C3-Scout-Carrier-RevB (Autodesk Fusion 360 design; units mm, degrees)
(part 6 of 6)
sketch "Antenna clearance cutout outline" plane through (0, 0, 0) normal (0, 0, 1) x axis (1, 0, 0)
  line L1 (23, 56) -> (11, 56)
  line L2 (23, 63) -> (23, 56)
  line L3 (11, 63) -> (23, 63)
  line L4 (11, 56) -> (11, 63)
extrude "Extrude2" cut sketch "Antenna clearance cutout outline" along normal blind 1.6
sketch "M3 NPTH clearance mounting holes profile" plane through (0, 0, 0) normal (0, 0, 1) x axis (1, 0, 0)
  circle C1 centre (3, 3) radius 1.7
  circle C2 centre (29, 3) radius 1.7
  circle C3 centre (3, 79) radius 1.7
  circle C4 centre (29, 79) radius 1.7
extrude "Extrude3" cut sketch "M3 NPTH clearance mounting holes profile" along normal blind 1.6
sketch "Plated holes 0.8 profile" plane through (0, 0, 0) normal (0, 0, 1) x axis (1, 0, 0)
  circle C1 centre (25.75, 16) radius 0.4
  circle C2 centre (28.25, 16) radius 0.4
extrude "Extrude4" cut sketch "Plated holes 0.8 profile" along normal blind 1.6
sketch "Plated holes 1.05 profile" plane through (0, 0, 0) normal (0, 0, 1) x axis (1, 0, 0)
  circle C1 centre (9.38, 77.14) radius 0.525
  circle C2 centre (9.38, 74.6) radius 0.525
  circle C3 centre (9.38, 72.06) radius 0.525
  circle C4 centre (9.38, 69.52) radius 0.525
  circle C5 centre (9.38, 66.98) radius 0.525
  circle C6 centre (9.38, 64.44) radius 0.525
  circle C7 centre (9.38, 61.9) radius 0.525
  circle C8 centre (9.38, 59.36) radius 0.525
  circle C9 centre (24.62, 77.14) radius 0.525
  circle C10 centre (24.62, 74.6) radius 0.525
  circle C11 centre (24.62, 72.06) radius 0.525
  circle C12 centre (24.62, 69.52) radius 0.525
  circle C13 centre (24.62, 66.98) radius 0.525
  circle C14 centre (24.62, 64.44) radius 0.525
  circle C15 centre (24.62, 61.9) radius 0.525
  circle C16 centre (24.62, 59.36) radius 0.525
extrude "Extrude5" cut sketch "Plated holes 1.05 profile" along normal blind 1.6
sketch "Plated holes 1.2 profile" plane through (0, 0, 0) normal (0, 0, 1) x axis (1, 0, 0)
  circle C1 centre (4, 17.25) radius 0.6
  circle C2 centre (4, 20.75) radius 0.6
  circle C3 centre (5, 7.45) radius 0.6
  circle C4 centre (5, 10.95) radius 0.6
  circle C5 centre (28, 7.75) radius 0.6
  circle C6 centre (28, 11.25) radius 0.6
  circle C7 centre (4, 47.25) radius 0.6
  circle C8 centre (4, 50.75) radius 0.6
extrude "Extrude6" cut sketch "Plated holes 1.2 profile" along normal blind 1.6
sketch "Plated holes 1.35 profile" plane through (0, 0, 0) normal (0, 0, 1) x axis (1, 0, 0)
  circle C1 centre (25.6, 19.68) radius 0.675
  circle C2 centre (29.4, 19.68) radius 0.675
  circle C3 centre (25.6, 28.32) radius 0.675
  circle C4 centre (29.4, 28.32) radius 0.675
extrude "Extrude7" cut sketch "Plated holes 1.35 profile" along normal blind 1.6
work_plane "WorkPlane1" AlongDistance 1.6 ExtraOffset 0
sketch "Exposed component pads profiles" plane through (0, 0, 1.6) normal (0, 0, 1) x axis (1, 0, 0)
  line L1 (14.15, 14.145) -> (12.45, 14.145)
  line L2 (14.15, 14.745) -> (14.15, 14.145)
  line L3 (12.45, 14.745) -> (14.15, 14.745)
  line L4 (12.45, 14.145) -> (12.45, 14.745)
  line L5 (19.55, 14.145) -> (17.85, 14.145)
  line L6 (19.55, 14.745) -> (19.55, 14.145)
  line L7 (17.85, 14.745) -> (19.55, 14.745)
  line L8 (17.85, 14.145) -> (17.85, 14.745)
  line L9 (14.15, 12.875) -> (12.45, 12.875)
  line L10 (14.15, 13.475) -> (14.15, 12.875)
  line L11 (12.45, 13.475) -> (14.15, 13.475)
  line L12 (12.45, 12.875) -> (12.45, 13.475)
  line L13 (19.55, 12.875) -> (17.85, 12.875)
  line L14 (19.55, 13.475) -> (19.55, 12.875)
  line L15 (17.85, 13.475) -> (19.55, 13.475)
  line L16 (17.85, 12.875) -> (17.85, 13.475)
  line L17 (14.15, 11.605) -> (12.45, 11.605)
  line L18 (14.15, 12.205) -> (14.15, 11.605)
  line L19 (12.45, 12.205) -> (14.15, 12.205)
  line L20 (12.45, 11.605) -> (12.45, 12.205)
  line L21 (19.55, 11.605) -> (17.85, 11.605)
  line L22 (19.55, 12.205) -> (19.55, 11.605)
  line L23 (17.85, 12.205) -> (19.55, 12.205)
  line L24 (17.85, 11.605) -> (17.85, 12.205)
  line L25 (14.15, 10.335) -> (12.45, 10.335)
  line L26 (14.15, 10.935) -> (14.15, 10.335)
  line L27 (12.45, 10.935) -> (14.15, 10.935)
  line L28 (12.45, 10.335) -> (12.45, 10.935)
  line L29 (19.55, 10.335) -> (17.85, 10.335)
  line L30 (19.55, 10.935) -> (19.55, 10.335)
  line L31 (17.85, 10.935) -> (19.55, 10.935)
  line L32 (17.85, 10.335) -> (17.85, 10.935)
  line L33 (14.15, 9.065) -> (12.45, 9.065)
  line L34 (14.15, 9.665) -> (14.15, 9.065)
  line L35 (12.45, 9.665) -> (14.15, 9.665)
  line L36 (12.45, 9.065) -> (12.45, 9.665)
  line L37 (19.55, 9.065) -> (17.85, 9.065)
  line L38 (19.55, 9.665) -> (19.55, 9.065)
  line L39 (17.85, 9.665) -> (19.55, 9.665)
  line L40 (17.85, 9.065) -> (17.85, 9.665)
  line L41 (14.15, 7.795) -> (12.45, 7.795)
  line L42 (14.15, 8.395) -> (14.15, 7.795)
  line L43 (12.45, 8.395) -> (14.15, 8.395)
  line L44 (12.45, 7.795) -> (12.45, 8.395)
  line L45 (19.55, 7.795) -> (17.85, 7.795)
  line L46 (19.55, 8.395) -> (19.55, 7.795)
  line L47 (17.85, 8.395) -> (19.55, 8.395)
  line L48 (17.85, 7.795) -> (17.85, 8.395)
  line L49 (14.15, 6.525) -> (12.45, 6.525)
  line L50 (14.15, 7.125) -> (14.15, 6.525)
  line L51 (12.45, 7.125) -> (14.15, 7.125)
  line L52 (12.45, 6.525) -> (12.45, 7.125)
  line L53 (19.55, 6.525) -> (17.85, 6.525)
  line L54 (19.55, 7.125) -> (19.55, 6.525)
  line L55 (17.85, 7.125) -> (19.55, 7.125)
  line L56 (17.85, 6.525) -> (17.85, 7.125)
  line L57 (14.15, 5.255) -> (12.45, 5.255)
  line L58 (14.15, 5.855) -> (14.15, 5.255)
  line L59 (12.45, 5.855) -> (14.15, 5.855)
  line L60 (12.45, 5.255) -> (12.45, 5.855)
  line L61 (19.55, 5.255) -> (17.85, 5.255)
  line L62 (19.55, 5.855) -> (19.55, 5.255)
  line L63 (17.85, 5.855) -> (19.55, 5.855)
  line L64 (17.85, 5.255) -> (17.85, 5.855)
  line L65 (9.15, 25.605) -> (7.45, 25.605)
  line L66 (9.15, 26.205) -> (9.15, 25.605)
  line L67 (7.45, 26.205) -> (9.15, 26.205)
  line L68 (7.45, 25.605) -> (7.45, 26.205)
  line L69 (14.55, 25.605) -> (12.85, 25.605)
  line L70 (14.55, 26.205) -> (14.55, 25.605)
  line L71 (12.85, 26.205) -> (14.55, 26.205)
  line L72 (12.85, 25.605) -> (12.85, 26.205)
  line L73 (9.15, 24.335) -> (7.45, 24.335)
  line L74 (9.15, 24.935) -> (9.15, 24.335)
  line L75 (7.45, 24.935) -> (9.15, 24.935)
  line L76 (7.45, 24.335) -> (7.45, 24.935)
  line L77 (14.55, 24.335) -> (12.85, 24.335)
  line L78 (14.55, 24.935) -> (14.55, 24.335)
  line L79 (12.85, 24.935) -> (14.55, 24.935)
  line L80 (12.85, 24.335) -> (12.85, 24.935)
  line L81 (9.15, 23.065) -> (7.45, 23.065)
  line L82 (9.15, 23.665) -> (9.15, 23.065)
  line L83 (7.45, 23.665) -> (9.15, 23.665)
  line L84 (7.45, 23.065) -> (7.45, 23.665)
  line L85 (14.55, 23.065) -> (12.85, 23.065)
  line L86 (14.55, 23.665) -> (14.55, 23.065)
  line L87 (12.85, 23.665) -> (14.55, 23.665)
  line L88 (12.85, 23.065) -> (12.85, 23.665)
  line L89 (9.15, 21.795) -> (7.45, 21.795)
  line L90 (9.15, 22.395) -> (9.15, 21.795)
  line L91 (7.45, 22.395) -> (9.15, 22.395)
  line L92 (7.45, 21.795) -> (7.45, 22.395)
  line L93 (14.55, 21.795) -> (12.85, 21.795)
  line L94 (14.55, 22.395) -> (14.55, 21.795)
  line L95 (12.85, 22.395) -> (14.55, 22.395)
  line L96 (12.85, 21.795) -> (12.85, 22.395)
  line L97 (12.125, 22.25) -> (9.875, 22.25)
  line L98 (12.125, 25.75) -> (12.125, 22.25)
  line L99 (9.875, 25.75) -> (12.125, 25.75)
  line L100 (9.875, 22.25) -> (9.875, 25.75)
  line L101 (4.875, 36.65) -> (3.825, 36.65)
  line L102 (4.875, 37.25) -> (4.875, 36.65)
  line L103 (3.825, 37.25) -> (4.875, 37.25)
  line L104 (3.825, 36.65) -> (3.825, 37.25)
  line L105 (7.175, 36.65) -> (6.125, 36.65)
  line L106 (7.175, 37.25) -> (7.175, 36.65)
  line L107 (6.125, 37.25) -> (7.175, 37.25)
  line L108 (6.125, 36.65) -> (6.125, 37.25)
  line L109 (4.875, 35.7) -> (3.825, 35.7)
  line L110 (4.875, 36.3) -> (4.875, 35.7)
  line L111 (3.825, 36.3) -> (4.875, 36.3)
  line L112 (3.825, 35.7) -> (3.825, 36.3)
  line L113 (7.175, 35.7) -> (6.125, 35.7)
  line L114 (7.175, 36.3) -> (7.175, 35.7)
  line L115 (6.125, 36.3) -> (7.175, 36.3)
  line L116 (6.125, 35.7) -> (6.125, 36.3)
  line L117 (4.875, 34.75) -> (3.825, 34.75)
  line L118 (4.875, 35.35) -> (4.875, 34.75)
  line L119 (3.825, 35.35) -> (4.875, 35.35)
  line L120 (3.825, 34.75) -> (3.825, 35.35)
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extrude "Extrude8" new body sketch "Exposed component pads profiles" along normal blind 0.035
work_plane "WorkPlane2" AlongDistance 1.6 ExtraOffset 0
sketch "Top plated annuli 0.95 profiles" plane through (0, 0, 1.6) normal (0, 0, 1) x axis (1, 0, 0)
  circle C1 centre (9.38, 77.14) radius 0.95
  circle C2 centre (9.38, 77.14) radius 0.525
  circle C3 centre (9.38, 74.6) radius 0.95
  circle C4 centre (9.38, 74.6) radius 0.525
  circle C5 centre (9.38, 72.06) radius 0.95
  circle C6 centre (9.38, 72.06) radius 0.525
  circle C7 centre (9.38, 69.52) radius 0.95
  circle C8 centre (9.38, 69.52) radius 0.525
  circle C9 centre (9.38, 66.98) radius 0.95
  circle C10 centre (9.38, 66.98) radius 0.525
  circle C11 centre (9.38, 64.44) radius 0.95
  circle C12 centre (9.38, 64.44) radius 0.525
  circle C13 centre (9.38, 61.9) radius 0.95
  circle C14 centre (9.38, 61.9) radius 0.525
  circle C15 centre (9.38, 59.36) radius 0.95
  circle C16 centre (9.38, 59.36) radius 0.525
  circle C17 centre (24.62, 77.14) radius 0.95
  circle C18 centre (24.62, 77.14) radius 0.525
  circle C19 centre (24.62, 74.6) radius 0.95
  circle C20 centre (24.62, 74.6) radius 0.525
  circle C21 centre (24.62, 72.06) radius 0.95
  circle C22 centre (24.62, 72.06) radius 0.525
  circle C23 centre (24.62, 69.52) radius 0.95
  circle C24 centre (24.62, 69.52) radius 0.525
  circle C25 centre (24.62, 66.98) radius 0.95
  circle C26 centre (24.62, 66.98) radius 0.525
  circle C27 centre (24.62, 64.44) radius 0.95
  circle C28 centre (24.62, 64.44) radius 0.525
  circle C29 centre (24.62, 61.9) radius 0.95
  circle C30 centre (24.62, 61.9) radius 0.525
  circle C31 centre (24.62, 59.36) radius 0.95
  circle C32 centre (24.62, 59.36) radius 0.525
extrude "Extrude9" new body sketch "Top plated annuli 0.95 profiles" along normal blind 0.035
work_plane "WorkPlane3" AlongDistance -0.035 ExtraOffset 0
sketch "Bottom plated annuli 0.95 profiles" plane through (0, 0, -0.035) normal (0, 0, 1) x axis (1, 0, 0)
  circle C1 centre (9.38, 77.14) radius 0.95
  circle C2 centre (9.38, 77.14) radius 0.525
  circle C3 centre (9.38, 74.6) radius 0.95
  circle C4 centre (9.38, 74.6) radius 0.525
  circle C5 centre (9.38, 72.06) radius 0.95
  circle C6 centre (9.38, 72.06) radius 0.525
  circle C7 centre (9.38, 69.52) radius 0.95
  circle C8 centre (9.38, 69.52) radius 0.525
  circle C9 centre (9.38, 66.98) radius 0.95
  circle C10 centre (9.38, 66.98) radius 0.525
  circle C11 centre (9.38, 64.44) radius 0.95
  circle C12 centre (9.38, 64.44) radius 0.525
  circle C13 centre (9.38, 61.9) radius 0.95
  circle C14 centre (9.38, 61.9) radius 0.525
  circle C15 centre (9.38, 59.36) radius 0.95
  circle C16 centre (9.38, 59.36) radius 0.525
  circle C17 centre (24.62, 77.14) radius 0.95
  circle C18 centre (24.62, 77.14) radius 0.525
  circle C19 centre (24.62, 74.6) radius 0.95
  circle C20 centre (24.62, 74.6) radius 0.525
  circle C21 centre (24.62, 72.06) radius 0.95
  circle C22 centre (24.62, 72.06) radius 0.525
  circle C23 centre (24.62, 69.52) radius 0.95
  circle C24 centre (24.62, 69.52) radius 0.525
  circle C25 centre (24.62, 66.98) radius 0.95
  circle C26 centre (24.62, 66.98) radius 0.525
  circle C27 centre (24.62, 64.44) radius 0.95
  circle C28 centre (24.62, 64.44) radius 0.525
  circle C29 centre (24.62, 61.9) radius 0.95
  circle C30 centre (24.62, 61.9) radius 0.525
  circle C31 centre (24.62, 59.36) radius 0.95
  circle C32 centre (24.62, 59.36) radius 0.525
extrude "Extrude10" new body sketch "Bottom plated annuli 0.95 profiles" along normal blind 0.035
work_plane "WorkPlane4" AlongDistance 1.6 ExtraOffset 0
sketch "Top plated annuli 1.1 profiles" plane through (0, 0, 1.6) normal (0, 0, 1) x axis (1, 0, 0)
  circle C1 centre (4, 17.25) radius 1.1
  circle C2 centre (4, 17.25) radius 0.6
  circle C3 centre (4, 20.75) radius 1.1
  circle C4 centre (4, 20.75) radius 0.6
  circle C5 centre (5, 7.45) radius 1.1
  circle C6 centre (5, 7.45) radius 0.6
  circle C7 centre (5, 10.95) radius 1.1
  circle C8 centre (5, 10.95) radius 0.6
  circle C9 centre (28, 7.75) radius 1.1
  circle C10 centre (28, 7.75) radius 0.6
  circle C11 centre (28, 11.25) radius 1.1
  circle C12 centre (28, 11.25) radius 0.6
  circle C13 centre (4, 47.25) radius 1.1
  circle C14 centre (4, 47.25) radius 0.6
  circle C15 centre (4, 50.75) radius 1.1
  circle C16 centre (4, 50.75) radius 0.6
extrude "Extrude11" new body sketch "Top plated annuli 1.1 profiles" along normal blind 0.035
work_plane "WorkPlane5" AlongDistance -0.035 ExtraOffset 0
sketch "Bottom plated annuli 1.1 profiles" plane through (0, 0, -0.035) normal (0, 0, 1) x axis (1, 0, 0)
  circle C1 centre (4, 17.25) radius 1.1
  circle C2 centre (4, 17.25) radius 0.6
  circle C3 centre (4, 20.75) radius 1.1
  circle C4 centre (4, 20.75) radius 0.6
  circle C5 centre (5, 7.45) radius 1.1
  circle C6 centre (5, 7.45) radius 0.6
  circle C7 centre (5, 10.95) radius 1.1
  circle C8 centre (5, 10.95) radius 0.6
  circle C9 centre (28, 7.75) radius 1.1
  circle C10 centre (28, 7.75) radius 0.6
  circle C11 centre (28, 11.25) radius 1.1
  circle C12 centre (28, 11.25) radius 0.6
  circle C13 centre (4, 47.25) radius 1.1
  circle C14 centre (4, 47.25) radius 0.6
  circle C15 centre (4, 50.75) radius 1.1
  circle C16 centre (4, 50.75) radius 0.6
extrude "Extrude12" new body sketch "Bottom plated annuli 1.1 profiles" along normal blind 0.035
work_plane "WorkPlane6" AlongDistance 1.6 ExtraOffset 0
sketch "Top plated annuli 1.0 profiles" plane through (0, 0, 1.6) normal (0, 0, 1) x axis (1, 0, 0)
  circle C1 centre (25.6, 19.68) radius 1
  circle C2 centre (25.6, 19.68) radius 0.675
  circle C3 centre (29.4, 19.68) radius 1
  circle C4 centre (29.4, 19.68) radius 0.675
  circle C5 centre (25.6, 28.32) radius 1
  circle C6 centre (25.6, 28.32) radius 0.675
  circle C7 centre (29.4, 28.32) radius 1
  circle C8 centre (29.4, 28.32) radius 0.675
extrude "Extrude13" new body sketch "Top plated annuli 1.0 profiles" along normal blind 0.035
work_plane "WorkPlane7" AlongDistance -0.035 ExtraOffset 0
sketch "Bottom plated annuli 1.0 profiles" plane through (0, 0, -0.035) normal (0, 0, 1) x axis (1, 0, 0)
  circle C1 centre (25.6, 19.68) radius 1
  circle C2 centre (25.6, 19.68) radius 0.675
  circle C3 centre (29.4, 19.68) radius 1
  circle C4 centre (29.4, 19.68) radius 0.675
  circle C5 centre (25.6, 28.32) radius 1
  circle C6 centre (25.6, 28.32) radius 0.675
  circle C7 centre (29.4, 28.32) radius 1
  circle C8 centre (29.4, 28.32) radius 0.675
extrude "Extrude14" new body sketch "Bottom plated annuli 1.0 profiles" along normal blind 0.035
work_plane "WorkPlane8" AlongDistance 1.6 ExtraOffset 0
sketch "Top plated annuli 0.9 profiles" plane through (0, 0, 1.6) normal (0, 0, 1) x axis (1, 0, 0)
  circle C1 centre (25.75, 16) radius 0.9
  circle C2 centre (25.75, 16) radius 0.4
  circle C3 centre (28.25, 16) radius 0.9
  circle C4 centre (28.25, 16) radius 0.4
extrude "Extrude15" new body sketch "Top plated annuli 0.9 profiles" along normal blind 0.035
work_plane "WorkPlane9" AlongDistance -0.035 ExtraOffset 0
sketch "Bottom plated annuli 0.9 profiles" plane through (0, 0, -0.035) normal (0, 0, 1) x axis (1, 0, 0)
  circle C1 centre (25.75, 16) radius 0.9
  circle C2 centre (25.75, 16) radius 0.4
  circle C3 centre (28.25, 16) radius 0.9
  circle C4 centre (28.25, 16) radius 0.4
extrude "Extrude16" new body sketch "Bottom plated annuli 0.9 profiles" along normal blind 0.035
work_plane "WorkPlane10" AlongDistance 1.64 ExtraOffset 0
sketch "SCOUT B marking" plane through (0, 0, 1.64) normal (0, 0, 1) x axis (1, 0, 0)
  dimension "d1570" = 1.5
extrude "Extrude17" new body sketch "SCOUT B marking" along normal blind 0.015
work_plane "WorkPlane11" AlongDistance 1.64 ExtraOffset 0
sketch "500mA marking" plane through (0, 0, 1.64) normal (0, 0, 1) x axis (1, 0, 0)
  dimension "d1576" = 1.05
  dimension "d1577" = "'500mA'"
extrude "Extrude18" new body sketch "500mA marking" along normal blind 0.015
work_plane "WorkPlane12" AlongDistance 1.64 ExtraOffset 0
sketch "RUN OFF marking" plane through (0, 0, 1.64) normal (0, 0, 1) x axis (1, 0, 0)
  dimension "d1582" = 1
extrude "Extrude19" new body sketch "RUN OFF marking" along normal blind 0.015
work_plane "WorkPlane1" AlongDistance -0.4 ExtraOffset 0
sketch "M3 shanks" plane through (0, 0, -0.4) normal (0, 0, 1) x axis (1, 0, 0)
  circle C1 centre (9.5, -10) radius 1.5
  circle C2 centre (35.5, -10) radius 1.5
  circle C3 centre (9.5, 66) radius 1.5
  circle C4 centre (35.5, 66) radius 1.5
extrude "Extrude1" new body sketch "M3 shanks" along normal blind 8
work_plane "WorkPlane2" AlongDistance 7.6 ExtraOffset 0
sketch "5.5 mm cap heads" plane through (0, 0, 7.6) normal (0, 0, 1) x axis (1, 0, 0)
  circle C1 centre (9.5, -10) radius 2.75
  circle C2 centre (35.5, -10) radius 2.75
  circle C3 centre (9.5, 66) radius 2.75
  circle C4 centre (35.5, 66) radius 2.75
extrude "Extrude2" add sketch "5.5 mm cap heads" along normal blind 3
work_plane "WorkPlane3" AlongDistance 9.3 ExtraOffset 0
sketch "2.5 mm Allen sockets profiles" plane through (0, 0, 9.3) normal (0, 0, 1) x axis (1, 0, 0)
  line L1 (10.2217, -8.75) -> (10.9434, -10)
  line L2 (8.7783, -8.75) -> (10.2217, -8.75)
  line L3 (8.0566, -10) -> (8.7783, -8.75)
  line L4 (8.7783, -11.25) -> (8.0566, -10)
  line L5 (10.2217, -11.25) -> (8.7783, -11.25)
  line L6 (10.9434, -10) -> (10.2217, -11.25)
  line L7 (36.2217, -8.75) -> (36.9434, -10)
  line L8 (34.7783, -8.75) -> (36.2217, -8.75)
  line L9 (34.0566, -10) -> (34.7783, -8.75)
  line L10 (34.7783, -11.25) -> (34.0566, -10)
  line L11 (36.2217, -11.25) -> (34.7783, -11.25)
  line L12 (36.9434, -10) -> (36.2217, -11.25)
  line L13 (10.2217, 67.25) -> (10.9434, 66)
  line L14 (8.7783, 67.25) -> (10.2217, 67.25)
  line L15 (8.0566, 66) -> (8.7783, 67.25)
  line L16 (8.7783, 64.75) -> (8.0566, 66)
  line L17 (10.2217, 64.75) -> (8.7783, 64.75)
  line L18 (10.9434, 66) -> (10.2217, 64.75)
  line L19 (36.2217, 67.25) -> (36.9434, 66)
  line L20 (34.7783, 67.25) -> (36.2217, 67.25)
  line L21 (34.0566, 66) -> (34.7783, 67.25)
  line L22 (34.7783, 64.75) -> (34.0566, 66)
  line L23 (36.2217, 64.75) -> (34.7783, 64.75)
  line L24 (36.9434, 66) -> (36.2217, 64.75)
extrude "Extrude3" cut sketch "2.5 mm Allen sockets profiles" along normal blind 1.3
work_plane "WorkPlane1" AlongDistance 0.2 ExtraOffset 0
sketch "M3 nut profiles" plane through (0, 0, 0.2) normal (0, 0, 1) x axis (1, 0, 0)
  line L1 (11.0877, -7.25) -> (12.6754, -10)
  line L2 (7.9123, -7.25) -> (11.0877, -7.25)
  line L3 (6.3246, -10) -> (7.9123, -7.25)
  line L4 (7.9123, -12.75) -> (6.3246, -10)
  line L5 (11.0877, -12.75) -> (7.9123, -12.75)
  line L6 (12.6754, -10) -> (11.0877, -12.75)
  line L7 (37.0877, -7.25) -> (38.6754, -10)
  line L8 (33.9123, -7.25) -> (37.0877, -7.25)
  line L9 (32.3246, -10) -> (33.9123, -7.25)
  line L10 (33.9123, -12.75) -> (32.3246, -10)
  line L11 (37.0877, -12.75) -> (33.9123, -12.75)
  line L12 (38.6754, -10) -> (37.0877, -12.75)
  line L13 (11.0877, 68.75) -> (12.6754, 66)
  line L14 (7.9123, 68.75) -> (11.0877, 68.75)
  line L15 (6.3246, 66) -> (7.9123, 68.75)
  line L16 (7.9123, 63.25) -> (6.3246, 66)
  line L17 (11.0877, 63.25) -> (7.9123, 63.25)
  line L18 (12.6754, 66) -> (11.0877, 63.25)
  line L19 (37.0877, 68.75) -> (38.6754, 66)
  line L20 (33.9123, 68.75) -> (37.0877, 68.75)
  line L21 (32.3246, 66) -> (33.9123, 68.75)
  line L22 (33.9123, 63.25) -> (32.3246, 66)
  line L23 (37.0877, 63.25) -> (33.9123, 63.25)
  line L24 (38.6754, 66) -> (37.0877, 63.25)
extrude "Extrude1" new body sketch "M3 nut profiles" along normal blind 2.4
work_plane "WorkPlane2" AlongDistance 0.2 ExtraOffset 0
sketch "Thread envelope clearance profile" plane through (0, 0, 0.2) normal (0, 0, 1) x axis (1, 0, 0)
  circle C1 centre (9.5, -10) radius 1.55
  circle C2 centre (35.5, -10) radius 1.55
  circle C3 centre (9.5, 66) radius 1.55
  circle C4 centre (35.5, 66) radius 1.55
extrude "Extrude2" cut sketch "Thread envelope clearance profile" along normal blind 2.4
work_plane "WorkPlane1" AlongDistance -3.4 ExtraOffset 0
sketch "M3 shanks" plane through (0, 0, -3.4) normal (0, 0, 1) x axis (1, 0, 0)
  circle C1 centre (-26, -42) radius 1.5
  circle C2 centre (-26, -22) radius 1.5
  circle C3 centre (26, -42) radius 1.5
  circle C4 centre (26, -22) radius 1.5
extrude "Extrude1" new body sketch "M3 shanks" along normal blind 16
work_plane "WorkPlane2" AlongDistance 12.6 ExtraOffset 0
sketch "5.5 mm cap heads" plane through (0, 0, 12.6) normal (0, 0, 1) x axis (1, 0, 0)
  circle C1 centre (-26, -42) radius 2.75
  circle C2 centre (-26, -22) radius 2.75
  circle C3 centre (26, -42) radius 2.75
  circle C4 centre (26, -22) radius 2.75
extrude "Extrude2" add sketch "5.5 mm cap heads" along normal blind 3
work_plane "WorkPlane3" AlongDistance 14.3 ExtraOffset 0
sketch "2.5 mm Allen sockets profiles" plane through (0, 0, 14.3) normal (0, 0, 1) x axis (1, 0, 0)
  line L1 (-25.2783, -40.75) -> (-24.5566, -42)
  line L2 (-26.7217, -40.75) -> (-25.2783, -40.75)
  line L3 (-27.4434, -42) -> (-26.7217, -40.75)
  line L4 (-26.7217, -43.25) -> (-27.4434, -42)
  line L5 (-25.2783, -43.25) -> (-26.7217, -43.25)
  line L6 (-24.5566, -42) -> (-25.2783, -43.25)
  line L7 (-25.2783, -20.75) -> (-24.5566, -22)
  line L8 (-26.7217, -20.75) -> (-25.2783, -20.75)
  line L9 (-27.4434, -22) -> (-26.7217, -20.75)
  line L10 (-26.7217, -23.25) -> (-27.4434, -22)
  line L11 (-25.2783, -23.25) -> (-26.7217, -23.25)
  line L12 (-24.5566, -22) -> (-25.2783, -23.25)
  line L13 (26.7217, -40.75) -> (27.4434, -42)
  line L14 (25.2783, -40.75) -> (26.7217, -40.75)
  line L15 (24.5566, -42) -> (25.2783, -40.75)
  line L16 (25.2783, -43.25) -> (24.5566, -42)
  line L17 (26.7217, -43.25) -> (25.2783, -43.25)
  line L18 (27.4434, -42) -> (26.7217, -43.25)
  line L19 (26.7217, -20.75) -> (27.4434, -22)
  line L20 (25.2783, -20.75) -> (26.7217, -20.75)
  line L21 (24.5566, -22) -> (25.2783, -20.75)
  line L22 (25.2783, -23.25) -> (24.5566, -22)
  line L23 (26.7217, -23.25) -> (25.2783, -23.25)
  line L24 (27.4434, -22) -> (26.7217, -23.25)
extrude "Extrude3" cut sketch "2.5 mm Allen sockets profiles" along normal blind 1.3
work_plane "WorkPlane1" AlongDistance -2.6 ExtraOffset 0
sketch "M3 nut profiles" plane through (0, 0, -2.6) normal (0, 0, 1) x axis (1, 0, 0)
  line L1 (-24.4123, -39.25) -> (-22.8246, -42)
  line L2 (-27.5877, -39.25) -> (-24.4123, -39.25)
  line L3 (-29.1754, -42) -> (-27.5877, -39.25)
  line L4 (-27.5877, -44.75) -> (-29.1754, -42)
  line L5 (-24.4123, -44.75) -> (-27.5877, -44.75)
  line L6 (-22.8246, -42) -> (-24.4123, -44.75)
  line L7 (-24.4123, -19.25) -> (-22.8246, -22)
  line L8 (-27.5877, -19.25) -> (-24.4123, -19.25)
  line L9 (-29.1754, -22) -> (-27.5877, -19.25)
  line L10 (-27.5877, -24.75) -> (-29.1754, -22)
  line L11 (-24.4123, -24.75) -> (-27.5877, -24.75)
  line L12 (-22.8246, -22) -> (-24.4123, -24.75)
  line L13 (27.5877, -39.25) -> (29.1754, -42)
  line L14 (24.4123, -39.25) -> (27.5877, -39.25)
  line L15 (22.8246, -42) -> (24.4123, -39.25)
  line L16 (24.4123, -44.75) -> (22.8246, -42)
  line L17 (27.5877, -44.75) -> (24.4123, -44.75)
  line L18 (29.1754, -42) -> (27.5877, -44.75)
  line L19 (27.5877, -19.25) -> (29.1754, -22)
  line L20 (24.4123, -19.25) -> (27.5877, -19.25)
  line L21 (22.8246, -22) -> (24.4123, -19.25)
  line L22 (24.4123, -24.75) -> (22.8246, -22)
  line L23 (27.5877, -24.75) -> (24.4123, -24.75)
  line L24 (29.1754, -22) -> (27.5877, -24.75)
extrude "Extrude1" new body sketch "M3 nut profiles" along normal blind 2.4
work_plane "WorkPlane2" AlongDistance -2.6 ExtraOffset 0
sketch "Thread envelope clearance profile" plane through (0, 0, -2.6) normal (0, 0, 1) x axis (1, 0, 0)
  circle C1 centre (-26, -42) radius 1.55
  circle C2 centre (-26, -22) radius 1.55
  circle C3 centre (26, -42) radius 1.55
  circle C4 centre (26, -22) radius 1.55
extrude "Extrude2" cut sketch "Thread envelope clearance profile" along normal blind 2.4
work_plane "WorkPlane1" AlongDistance -4 ExtraOffset 0
sketch "M3 shanks" plane through (0, 0, -4) normal (0, 0, 1) x axis (1, 0, 0)
  circle C1 centre (-28, -49) radius 1.5
  circle C2 centre (28, -49) radius 1.5
extrude "Extrude1" new body sketch "M3 shanks" along normal blind 10
work_plane "WorkPlane2" AlongDistance 6 ExtraOffset 0
sketch "5.5 mm cap heads" plane through (0, 0, 6) normal (0, 0, 1) x axis (1, 0, 0)
  circle C1 centre (-28, -49) radius 2.75
  circle C2 centre (28, -49) radius 2.75
extrude "Extrude2" add sketch "5.5 mm cap heads" along normal blind 3
work_plane "WorkPlane3" AlongDistance 7.7 ExtraOffset 0
sketch "2.5 mm Allen sockets profiles" plane through (0, 0, 7.7) normal (0, 0, 1) x axis (1, 0, 0)
  line L1 (-27.2783, -47.75) -> (-26.5566, -49)
  line L2 (-28.7217, -47.75) -> (-27.2783, -47.75)
  line L3 (-29.4434, -49) -> (-28.7217, -47.75)
  line L4 (-28.7217, -50.25) -> (-29.4434, -49)
  line L5 (-27.2783, -50.25) -> (-28.7217, -50.25)
  line L6 (-26.5566, -49) -> (-27.2783, -50.25)
  line L7 (28.7217, -47.75) -> (29.4434, -49)
  line L8 (27.2783, -47.75) -> (28.7217, -47.75)
  line L9 (26.5566, -49) -> (27.2783, -47.75)
  line L10 (27.2783, -50.25) -> (26.5566, -49)
  line L11 (28.7217, -50.25) -> (27.2783, -50.25)
  line L12 (29.4434, -49) -> (28.7217, -50.25)
extrude "Extrude3" cut sketch "2.5 mm Allen sockets profiles" along normal blind 1.3
work_plane "WorkPlane1" AlongDistance -2.6 ExtraOffset 0
sketch "M3 nut profiles" plane through (0, 0, -2.6) normal (0, 0, 1) x axis (1, 0, 0)
  line L1 (-26.4123, -46.25) -> (-24.8246, -49)
  line L2 (-29.5877, -46.25) -> (-26.4123, -46.25)
  line L3 (-31.1754, -49) -> (-29.5877, -46.25)
  line L4 (-29.5877, -51.75) -> (-31.1754, -49)
  line L5 (-26.4123, -51.75) -> (-29.5877, -51.75)
  line L6 (-24.8246, -49) -> (-26.4123, -51.75)
  line L7 (29.5877, -46.25) -> (31.1754, -49)
  line L8 (26.4123, -46.25) -> (29.5877, -46.25)
  line L9 (24.8246, -49) -> (26.4123, -46.25)
  line L10 (26.4123, -51.75) -> (24.8246, -49)
  line L11 (29.5877, -51.75) -> (26.4123, -51.75)
  line L12 (31.1754, -49) -> (29.5877, -51.75)
extrude "Extrude1" new body sketch "M3 nut profiles" along normal blind 2.4
work_plane "WorkPlane2" AlongDistance -2.6 ExtraOffset 0
sketch "Thread envelope clearance profile" plane through (0, 0, -2.6) normal (0, 0, 1) x axis (1, 0, 0)
  circle C1 centre (-28, -49) radius 1.55
  circle C2 centre (28, -49) radius 1.55
extrude "Extrude2" cut sketch "Thread envelope clearance profile" along normal blind 2.4
work_plane "WorkPlane1" AlongDistance -7 ExtraOffset 0
sketch "M3 shanks" plane through (0, 0, -7) normal (0, 0, 1) x axis (1, 0, 0)
  circle C1 centre (2, 52) radius 1.5
  circle C2 centre (2, 60) radius 1.5
extrude "Extrude1" new body sketch "M3 shanks" along normal blind 10
work_plane "WorkPlane2" AlongDistance 3 ExtraOffset 0
sketch "5.5 mm cap heads" plane through (0, 0, 3) normal (0, 0, 1) x axis (1, 0, 0)
  circle C1 centre (2, 52) radius 2.75
  circle C2 centre (2, 60) radius 2.75
extrude "Extrude2" add sketch "5.5 mm cap heads" along normal blind 3
work_plane "WorkPlane3" AlongDistance 4.7 ExtraOffset 0
sketch "2.5 mm Allen sockets profiles" plane through (0, 0, 4.7) normal (0, 0, 1) x axis (1, 0, 0)
  line L1 (2.7217, 53.25) -> (3.4434, 52)
  line L2 (1.2783, 53.25) -> (2.7217, 53.25)
  line L3 (0.5566, 52) -> (1.2783, 53.25)
  line L4 (1.2783, 50.75) -> (0.5566, 52)
  line L5 (2.7217, 50.75) -> (1.2783, 50.75)
  line L6 (3.4434, 52) -> (2.7217, 50.75)
  line L7 (2.7217, 61.25) -> (3.4434, 60)
  line L8 (1.2783, 61.25) -> (2.7217, 61.25)
  line L9 (0.5566, 60) -> (1.2783, 61.25)
  line L10 (1.2783, 58.75) -> (0.5566, 60)
  line L11 (2.7217, 58.75) -> (1.2783, 58.75)
  line L12 (3.4434, 60) -> (2.7217, 58.75)
extrude "Extrude3" cut sketch "2.5 mm Allen sockets profiles" along normal blind 1.3
work_plane "WorkPlane1" AlongDistance -6.6 ExtraOffset 0
sketch "M3 nut profiles" plane through (0, 0, -6.6) normal (0, 0, 1) x axis (1, 0, 0)
  line L1 (3.5877, 54.75) -> (5.1754, 52)
  line L2 (0.4123, 54.75) -> (3.5877, 54.75)
  line L3 (-1.1754, 52) -> (0.4123, 54.75)
  line L4 (0.4123, 49.25) -> (-1.1754, 52)
  line L5 (3.5877, 49.25) -> (0.4123, 49.25)
  line L6 (5.1754, 52) -> (3.5877, 49.25)
  line L7 (3.5877, 62.75) -> (5.1754, 60)
  line L8 (0.4123, 62.75) -> (3.5877, 62.75)
  line L9 (-1.1754, 60) -> (0.4123, 62.75)
  line L10 (0.4123, 57.25) -> (-1.1754, 60)
  line L11 (3.5877, 57.25) -> (0.4123, 57.25)
  line L12 (5.1754, 60) -> (3.5877, 57.25)
extrude "Extrude1" new body sketch "M3 nut profiles" along normal blind 2.4
work_plane "WorkPlane2" AlongDistance -6.6 ExtraOffset 0
sketch "Thread envelope clearance profile" plane through (0, 0, -6.6) normal (0, 0, 1) x axis (1, 0, 0)
  circle C1 centre (2, 52) radius 1.55
  circle C2 centre (2, 60) radius 1.55
extrude "Extrude2" cut sketch "Thread envelope clearance profile" along normal blind 2.4
position "Position8"
sketch "M3 corner support profiles" plane through (0, 0, 0) normal (0, 0, 1) x axis (1, 0, 0)
  line L1 (1, 0) -> (0, 1)
  line L2 (2.1, 0) -> (1, 0)
  line L3 (0, 2.1) -> (2.1, 0)
  line L4 (0, 1) -> (0, 2.1)
  line L5 (31, 0) -> (32, 1)
  line L6 (29.9, 0) -> (31, 0)
  line L7 (32, 2.1) -> (29.9, 0)
  line L8 (32, 1) -> (32, 2.1)
  line L9 (31, 82) -> (32, 81)
  line L10 (29.9, 82) -> (31, 82)
  line L11 (32, 79.9) -> (29.9, 82)
  line L12 (32, 81) -> (32, 79.9)
  line L13 (1, 82) -> (0, 81)
  line L14 (2.1, 82) -> (1, 82)
  line L15 (0, 79.9) -> (2.1, 82)
  line L16 (0, 81) -> (0, 79.9)
extrude "Extrude20" add sketch "M3 corner support profiles" along normal blind 1.6
work_plane "WorkPlane5" AlongDistance 9.6 ExtraOffset 0
sketch "M3 clamp end reinforcement profile" plane through (0, 0, 9.6) normal (0, 0, 1) x axis (1, 0, 0)
  line L1 (4, -13.35) -> (-4, -13.35)
  line L2 (4, -12.95) -> (4, -13.35)
  line L3 (-4, -12.95) -> (4, -12.95)
  line L4 (-4, -13.35) -> (-4, -12.95)
  line L5 (4, 12.95) -> (-4, 12.95)
  line L6 (4, 13.35) -> (4, 12.95)
  line L7 (-4, 13.35) -> (4, 13.35)
  line L8 (-4, 12.95) -> (-4, 13.35)
extrude "Extrude10" add sketch "M3 clamp end reinforcement profile" along normal blind 3.2
work_plane "WorkPlane6" AlongDistance 9.6 ExtraOffset 0
sketch "Reopen reinforced M3 head pockets profile" plane through (0, 0, 9.6) normal (0, 0, 1) x axis (1, 0, 0)
  circle C1 centre (0, -10) radius 3.1
  circle C2 centre (0, 10) radius 3.1
extrude "Extrude11" cut sketch "Reopen reinforced M3 head pockets profile" along normal blind 3.2
work_plane "WorkPlane7" AlongDistance 12.8 ExtraOffset 0
sketch "Flat bridge print face profile" plane through (0, 0, 12.8) normal (0, 0, 1) x axis (1, 0, 0)
  line L1 (6, -14) -> (-6, -14)
  line L2 (6, 14) -> (6, -14)
  line L3 (-6, 14) -> (6, 14)
  line L4 (-6, -14) -> (-6, 14)
work_plane "WorkPlane8" AlongDistance 12.4 ExtraOffset 0
sketch "Recessed bridge chevron outline" plane through (0, 0, 12.4) normal (0, 0, 1) x axis (1, 0, 0)
  line L1 (1.2, -4) -> (-1.2, -4)
  line L2 (1.2, 2.5) -> (1.2, -4)
  line L3 (0, 4) -> (1.2, 2.5)
  line L4 (-1.2, 2.5) -> (0, 4)
  line L5 (-1.2, -4) -> (-1.2, 2.5)
work_plane "WorkPlane5" AlongDistance 9.6 ExtraOffset 0
sketch "M3 clamp end reinforcement profile" plane through (0, 0, 9.6) normal (0, 0, 1) x axis (1, 0, 0)
  line L1 (4, -13.35) -> (-4, -13.35)
  line L2 (4, -12.95) -> (4, -13.35)
  line L3 (-4, -12.95) -> (4, -12.95)
  line L4 (-4, -13.35) -> (-4, -12.95)
  line L5 (4, 12.95) -> (-4, 12.95)
  line L6 (4, 13.35) -> (4, 12.95)
  line L7 (-4, 13.35) -> (4, 13.35)
  line L8 (-4, 12.95) -> (-4, 13.35)
extrude "Extrude10" add sketch "M3 clamp end reinforcement profile" along normal blind 3.2
work_plane "WorkPlane6" AlongDistance 9.6 ExtraOffset 0
sketch "Reopen reinforced M3 head pockets profile" plane through (0, 0, 9.6) normal (0, 0, 1) x axis (1, 0, 0)
  circle C1 centre (0, -10) radius 3.1
  circle C2 centre (0, 10) radius 3.1
extrude "Extrude11" cut sketch "Reopen reinforced M3 head pockets profile" along normal blind 3.2
work_plane "WorkPlane7" AlongDistance 12.8 ExtraOffset 0
sketch "Flat bridge print face profile" plane through (0, 0, 12.8) normal (0, 0, 1) x axis (1, 0, 0)
  line L1 (6, -14) -> (-6, -14)
  line L2 (6, 14) -> (6, -14)
  line L3 (-6, 14) -> (6, 14)
  line L4 (-6, -14) -> (-6, 14)
work_plane "WorkPlane8" AlongDistance 12.4 ExtraOffset 0
sketch "Recessed bridge chevron outline" plane through (0, 0, 12.4) normal (0, 0, 1) x axis (1, 0, 0)
  line L1 (1.2, -4) -> (-1.2, -4)
  line L2 (1.2, 2.5) -> (1.2, -4)
  line L3 (0, 4) -> (1.2, 2.5)
  line L4 (-1.2, 2.5) -> (0, 4)
  line L5 (-1.2, -4) -> (-1.2, 2.5)
work_plane "WorkPlane1" AlongDistance 6.05 ExtraOffset 0
sketch "8 mm tail driver gauge 52 profile" plane through (0, 0, 6.05) normal (0, 0, 1) x axis (1, 0, 0)
  circle C1 centre (2, 52) radius 4
extrude "Extrude1" new body sketch "8 mm tail driver gauge 52 profile" along normal blind 30 bodies "Tail driver 8 mm at Y 52"
work_plane "WorkPlane2" AlongDistance 6.05 ExtraOffset 0
sketch "8 mm tail driver gauge 60 profile" plane through (0, 0, 6.05) normal (0, 0, 1) x axis (1, 0, 0)
  circle C1 centre (2, 60) radius 4
extrude "Extrude2" new body sketch "8 mm tail driver gauge 60 profile" along normal blind 30 bodies "Tail driver 8 mm at Y 60"
work_plane "WorkPlane3" AlongDistance 6.6 ExtraOffset 0
sketch "Side USB plug envelope profile" plane through (0, 0, 6.6) normal (0, 0, 1) x axis (1, 0, 0)
  line L1 (55, 4.6) -> (38.6, 4.6)
  line L2 (55, 17.4) -> (55, 4.6)
  line L3 (38.6, 17.4) -> (55, 17.4)
  line L4 (38.6, 4.6) -> (38.6, 17.4)
extrude "Extrude3" new body sketch "Side USB plug envelope profile" along normal blind 5.7 bodies "Charging USB cable insertion"
work_plane "WorkPlane4" AlongDistance 9.8 ExtraOffset 0
sketch "Rear USB plug envelope profile" plane through (0, 0, 9.8) normal (0, 0, 1) x axis (1, 0, 0)
  line L1 (30, 69.4) -> (17, 69.4)
  line L2 (30, 89.4) -> (30, 69.4)
  line L3 (17, 89.4) -> (30, 89.4)
  line L4 (17, 69.4) -> (17, 89.4)
extrude "Extrude4" new body sketch "Rear USB plug envelope profile" along normal blind 6 bodies "Programming USB cable insertion"
work_plane "WorkPlane21" AlongDistance 3 ExtraOffset 0
sketch "Open battery holder well profile" plane through (0, 0, 3) normal (0, 0, 1) x axis (1, 0, 0)
  line L1 (-4, -16) -> (-28, -16)
  line L2 (-4, 64) -> (-4, -16)
  line L3 (-28, 64) -> (-4, 64)
  line L4 (-28, -16) -> (-28, 64)
extrude "Extrude35" cut sketch "Open battery holder well profile" along normal blind 4.5
work_plane "WorkPlane22" AlongDistance 3 ExtraOffset 0
sketch "Continuous rear corner web outline" plane through (0, 0, 3) normal (0, 0, 1) x axis (1, 0, 0)
  line L1 (39.4, 68.9) -> (38.4, 68.9)
  line L2 (38.4, 69.9) -> (39.4, 68.9)
  line L3 (38.4, 68.9) -> (38.4, 69.9)
extrude "Extrude36" add sketch "Continuous rear corner web outline" along normal blind 5.4
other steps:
create_component "CreateComponent1"
create_component "CreateComponent1"
create_component "CreateComponent2"
create_component "CreateComponent3"
create_component "CreateComponent4"
create_component "CreateComponent5"
create_component "CreateComponent6"
create_component "CreateComponent7"
create_component "CreateComponent8"
create_component "CreateComponent9"
create_component "CreateComponent10"
create_component "CreateComponent11"
create_component "CreateComponent12"
create_component "CreateComponent13"
create_component "CreateComponent14"
create_component "CreateComponent15"
create_component "CreateComponent16"
create_component "CreateComponent17" sketch "Contact plate profile"
create_component "CreateComponent18"
create_component "CreateComponent1"
create_component "CreateComponent19"
create_component "CreateComponent1"
create_component "CreateComponent20"
create_component "CreateComponent1"
create_component "CreateComponent21"
create_component "CreateComponent22"
create_component "CreateComponent23"
create_component "CreateComponent24" sketch "Retention strap cross section"
create_component "CreateComponent25" sketch "Retention strap cross section"
create_component "CreateComponent26"
create_component "CreateComponent27"
create_component "CreateComponent28"
create_component "CreateComponent29"
create_component "CreateComponent30"
create_component "CreateComponent31"
create_component "CreateComponent32"
create_component "CreateComponent33"
create_component "CreateComponent34"
create_component "CreateComponent35"
create_component "CreateComponent36"
create_component "CreateComponent37"
create_component "CreateComponent38"
create_component "CreateComponent39"
create_component "CreateComponent40"
create_component "CreateComponent41"
create_component "CreateComponent42"
create_component "CreateComponent43"
create_component "CreateComponent44"
create_component "CreateComponent45"
create_component "CreateComponent46"
create_component "CreateComponent47"
create_component "CreateComponent48"
create_component "CreateComponent49"
create_component "CreateComponent50"
create_component "CreateComponent51"
create_component "CreateComponent52"
create_component "CreateComponent53"
create_component "CreateComponent54"
create_component "CreateComponent55"
create_component "CreateComponent56"
create_component "CreateComponent57"
create_component "CreateComponent58"
create_component "CreateComponent59"
create_component "CreateComponent60"
create_component "CreateComponent61"
create_component "CreateComponent62"
create_component "CreateComponent63"
create_component "CreateComponent64"
create_component "CreateComponent65"
create_component "CreateComponent66"
create_component "CreateComponent67"
create_component "CreateComponent68"
create_component "CreateComponent69"
create_component "CreateComponent70"
create_component "CreateComponent71"
create_component "CreateComponent72"
create_component "CreateComponent73"
create_component "CreateComponent74"
create_component "CreateComponent75"
create_component "CreateComponent76"
create_component "CreateComponent77"
create_component "CreateComponent78"
create_component "CreateComponent79"
create_component "CreateComponent80"
create_component "CreateComponent81"
create_component "CreateComponent82"
create_component "CreateComponent83"
create_component "CreateComponent84"
create_component "CreateComponent85"
create_component "CreateComponent86"
create_component "CreateComponent87"
create_component "CreateComponent88"
create_component "CreateComponent89"
create_component "CreateComponent90"
create_component "CreateComponent91"
create_component "CreateComponent92"
create_component "CreateComponent93"
create_component "CreateComponent94"
named bodies: "Scout chassis", "Integral chassis and carrier bay", "Tail driver 8 mm at Y 52", "Tail driver 8 mm at Y 60", "Charging USB cable insertion", "Programming USB cable insertion"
